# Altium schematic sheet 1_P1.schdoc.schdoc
size 309 x 223 mm; Symbol: Sheet-Symbol_A4; Device: Sheet-Symbol_A4; @Page Name: P1; @Create Date: 2023-12-06; @Page Count: 1; @Page No: 1; @Project Name: TauKeyboard; @Schematic Name: 87key; @Update Date: 2023-12-06; Company: 嘉立创EDA; Page Size: A4; Version: V1.0
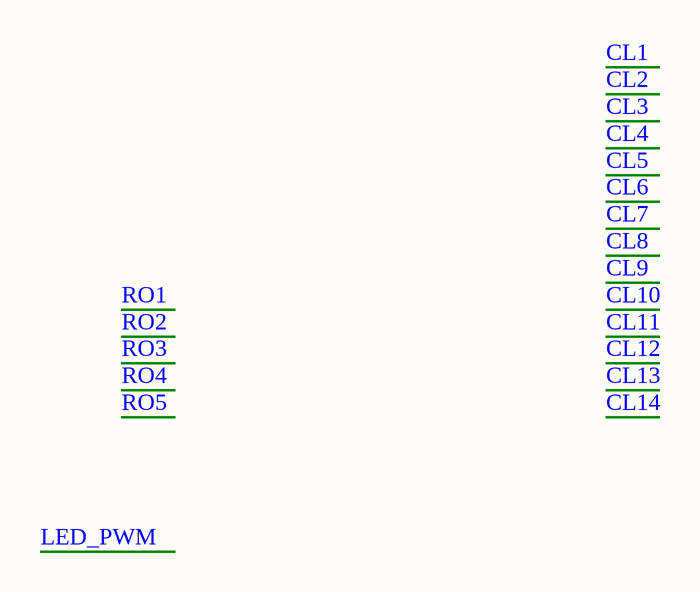
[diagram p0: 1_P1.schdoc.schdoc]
